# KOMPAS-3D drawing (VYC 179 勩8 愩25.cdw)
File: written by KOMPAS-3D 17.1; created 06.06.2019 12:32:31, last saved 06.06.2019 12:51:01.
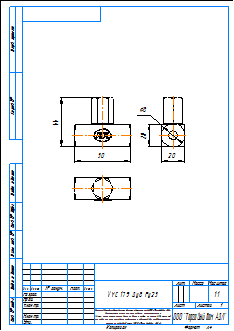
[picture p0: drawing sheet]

Sheet 1: A4, portrait

Title block, sheet 1: name: VYC 179 Ду8 Ру25; material: Внимание! Данный продукт является объектом авторского права ООО «Торговый Дом АДЛ». / Запрещается изменение, копирование, распространение / (в том числе путем копирования на другие сайты и ресурсы в Интернете) / или любое иное использование информации и объектов без предварительного / согласия правообладателя (ООО «Торговый Дом АДЛ»).; sheets: 1; organisation: ООО "Торговый дом АДЛ"; sheet format: A4; stored path: \\adlc.lan\data\АДЛ_ПКД\3D-модели\Поставщики\VYC Industrial\VYC 179\KOMPAS 2D\VYC 179 Ду8 Ру25.cdw

Views: Вид 1, Проекционный вид 2, Проекционный вид 3
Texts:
  user
Dimensions and other numbers on the sheet: 44; 50; 20; 8; 1:1; 1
